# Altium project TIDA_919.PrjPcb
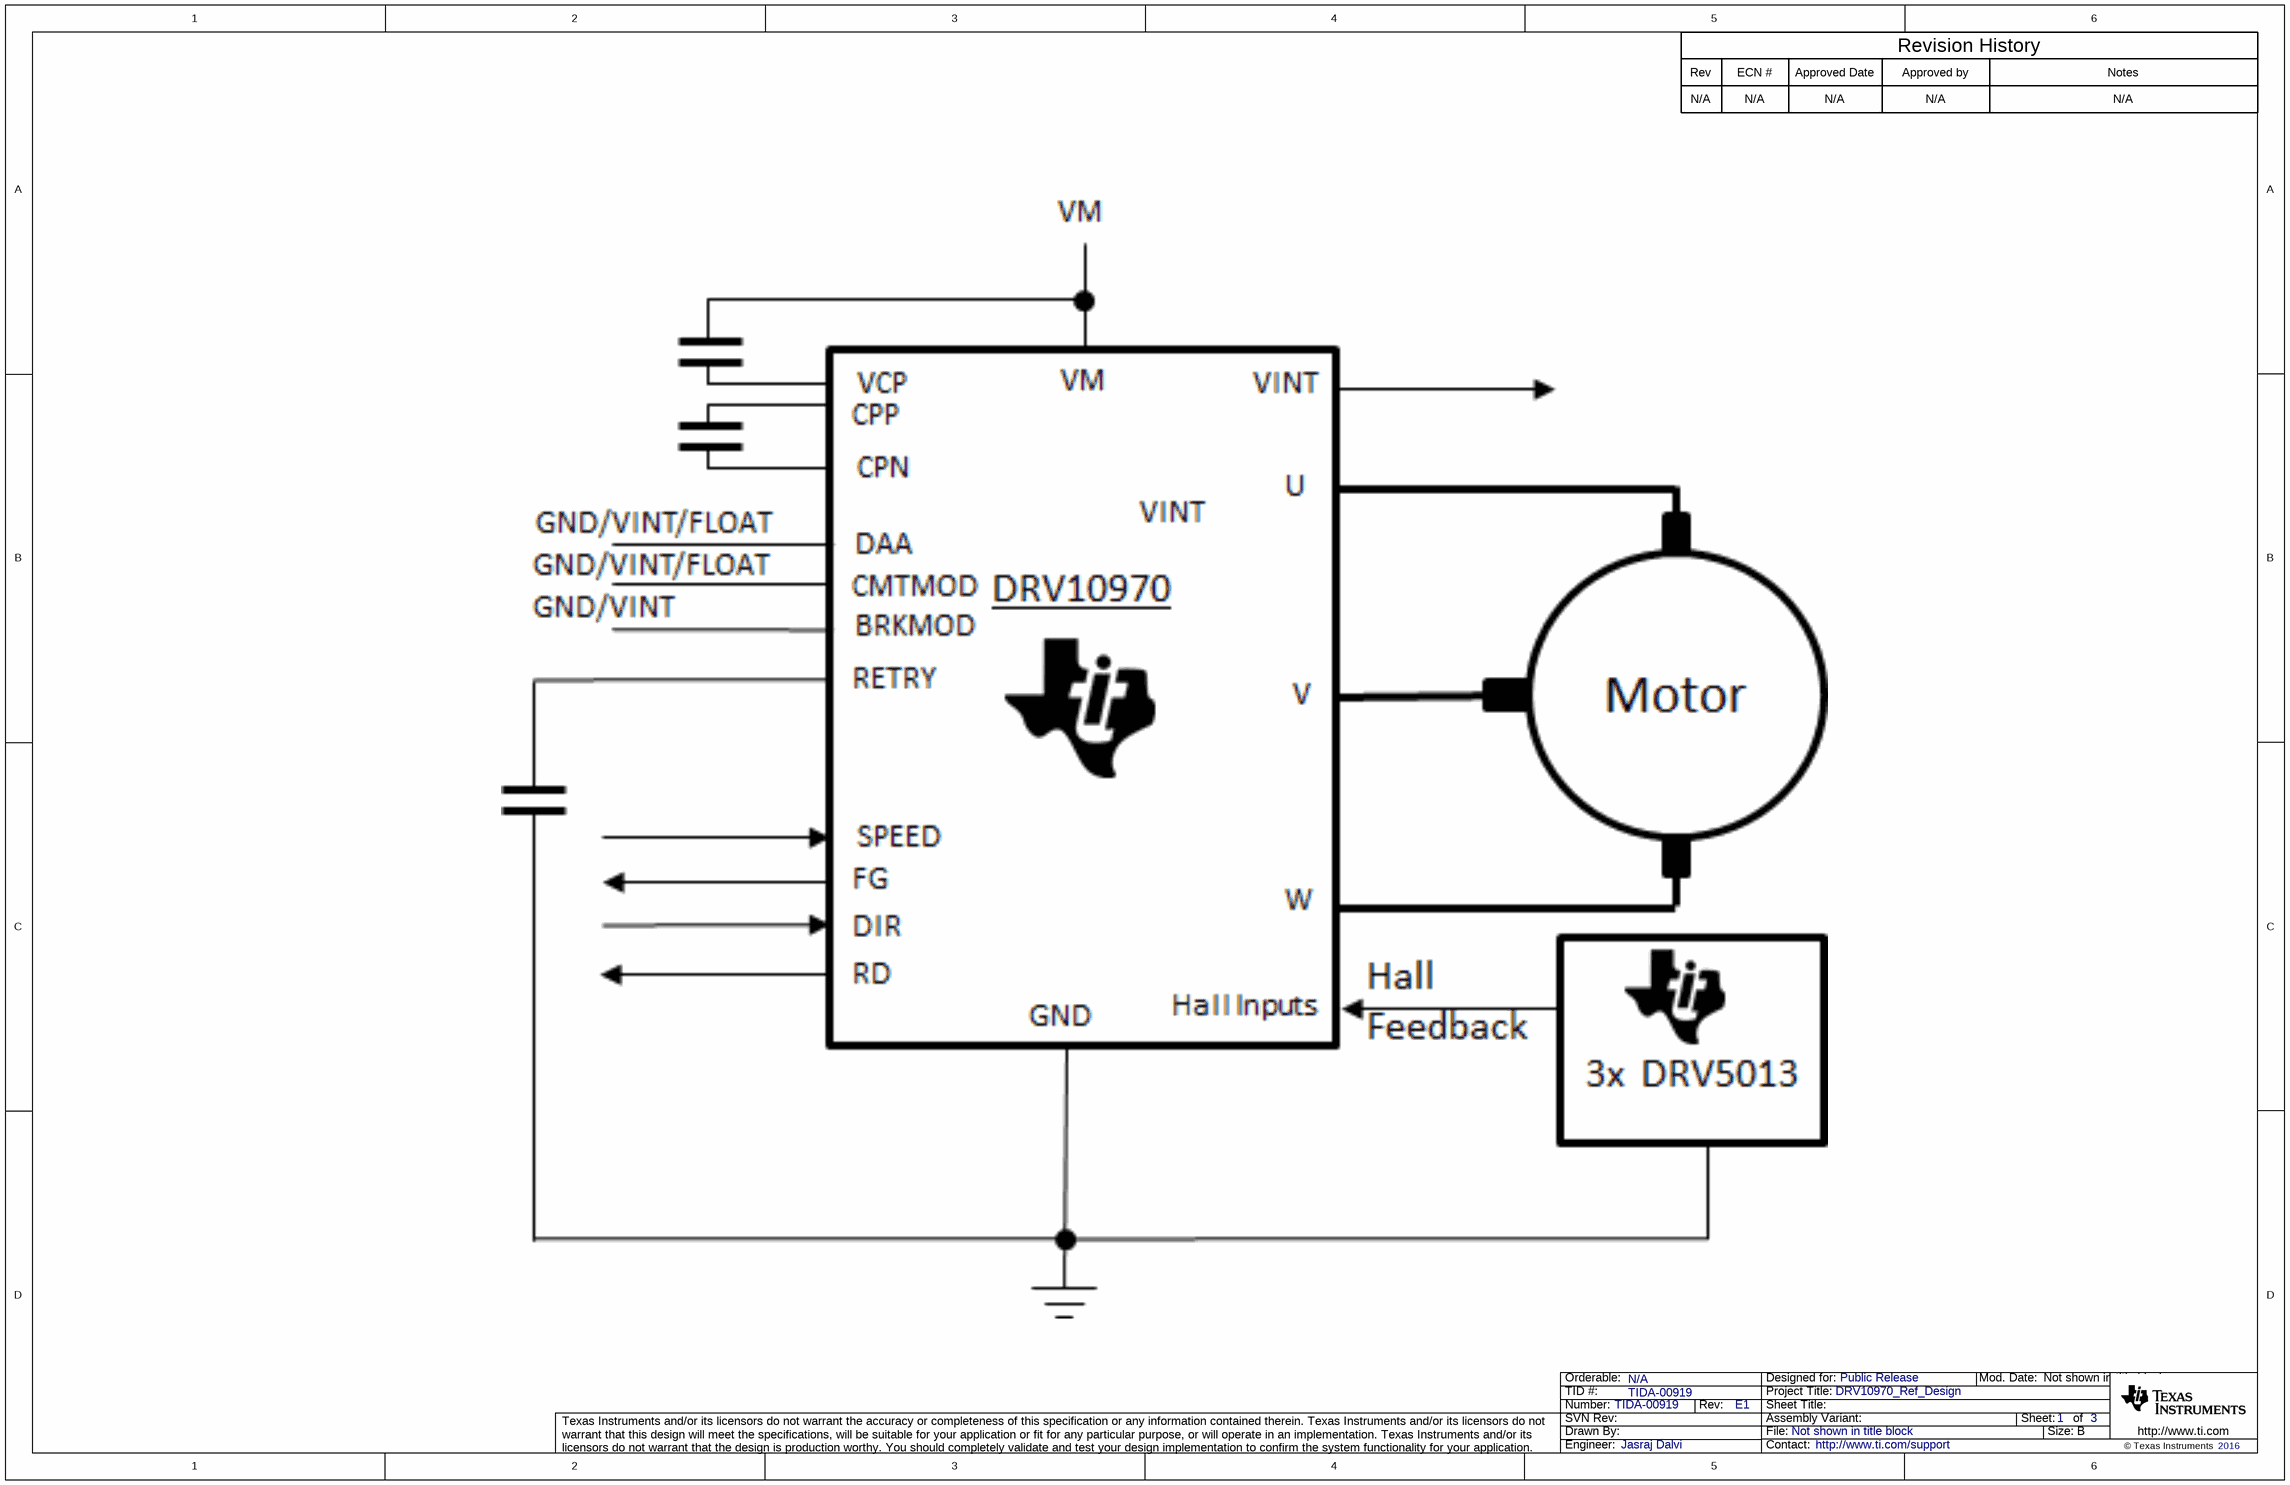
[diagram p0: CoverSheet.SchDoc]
CopyrightYear: 2016; EVM_Orderable: N/A; PCB_Layout: Jasraj Dalvi; PCB_Rev: E1; PRJ_Customer: Public Release; PRJ_Engineer: Jasraj Dalvi; PRJ_Number: TIDA-00919; PRJ_Title: DRV10970_Ref_Design; SCH_Rev: E1; TechSupport: http://www.ti.com/support; TID: TIDA-00919
3 sheets, 38 parts. Net scope: global (net labels, ports and power ports of the same name join across sheets).
Board file: TIDA00919E1.PcbDoc
Sheets:
  CoverSheet.SchDoc
  TIDA_00919.SchDoc
  TID_Hardware.SchDoc

## Sheet CoverSheet.SchDoc
size 431 x 279 mm; Date: Not shown in title block; ApprovedBy: Not shown in title block; CheckedBy: Not shown in title block; Author: Not shown in title block; CompanyName: Not shown in title block; Engineer: Not shown in title block; Organization: Not shown in title block; Address1: Not shown in title block; Address2: Not shown in title block; Address3: Not shown in title block; Address4: Not shown in title block; DocumentNumber: 1; Revision: Use project parameter SCH_Rev; SheetNumber: 1; SheetTotal: 3; PageSetup: Record=PageOptions¦CenterHorizontal=True¦CenterVertical=True¦PrintScale=1.00¦XCorrection=1.00¦YCorrection=1.00¦PrintKind=0¦BorderSize=5000000¦LeftOffset=0¦BottomOffset=0¦Orientation=2¦PaperLength=1000¦PaperWidth=1000¦Scale=100¦PaperSource=15¦PrintQuality=600¦MediaType=1¦DitherType=10¦PaperKind=Letter¦PrintScaleMode=1

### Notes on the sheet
- Rev
- N/A
- ECN #
- Approved Date
- Approved by
- Revision History
- Notes

## Sheet TIDA_00919.SchDoc
size 431 x 279 mm; Date: Not shown in title block; ApprovedBy: Not shown in title block; CheckedBy: Not shown in title block; Author: Not shown in title block; CompanyName: Not shown in title block; Engineer: Not shown in title block; Organization: Not shown in title block; Address1: Not shown in title block; Address2: Not shown in title block; Address3: Not shown in title block; Address4: Not shown in title block; DocumentNumber: 1; Revision: Use project parameter SCH_Rev; SheetNumber: 2; SheetTotal: 3; PageSetup: Record=PageOptions¦CenterHorizontal=True¦CenterVertical=True¦PrintScale=0.62¦XCorrection=1.00¦YCorrection=1.00¦PrintKind=0¦BorderSize=5000000¦LeftOffset=0¦BottomOffset=0¦Orientation=2¦PaperLength=1000¦PaperWidth=1000¦Scale=100¦PaperSource=15¦PrintQuality=600¦MediaType=1¦DitherType=10¦PrintScaleMode=1¦PaperKind=Letter
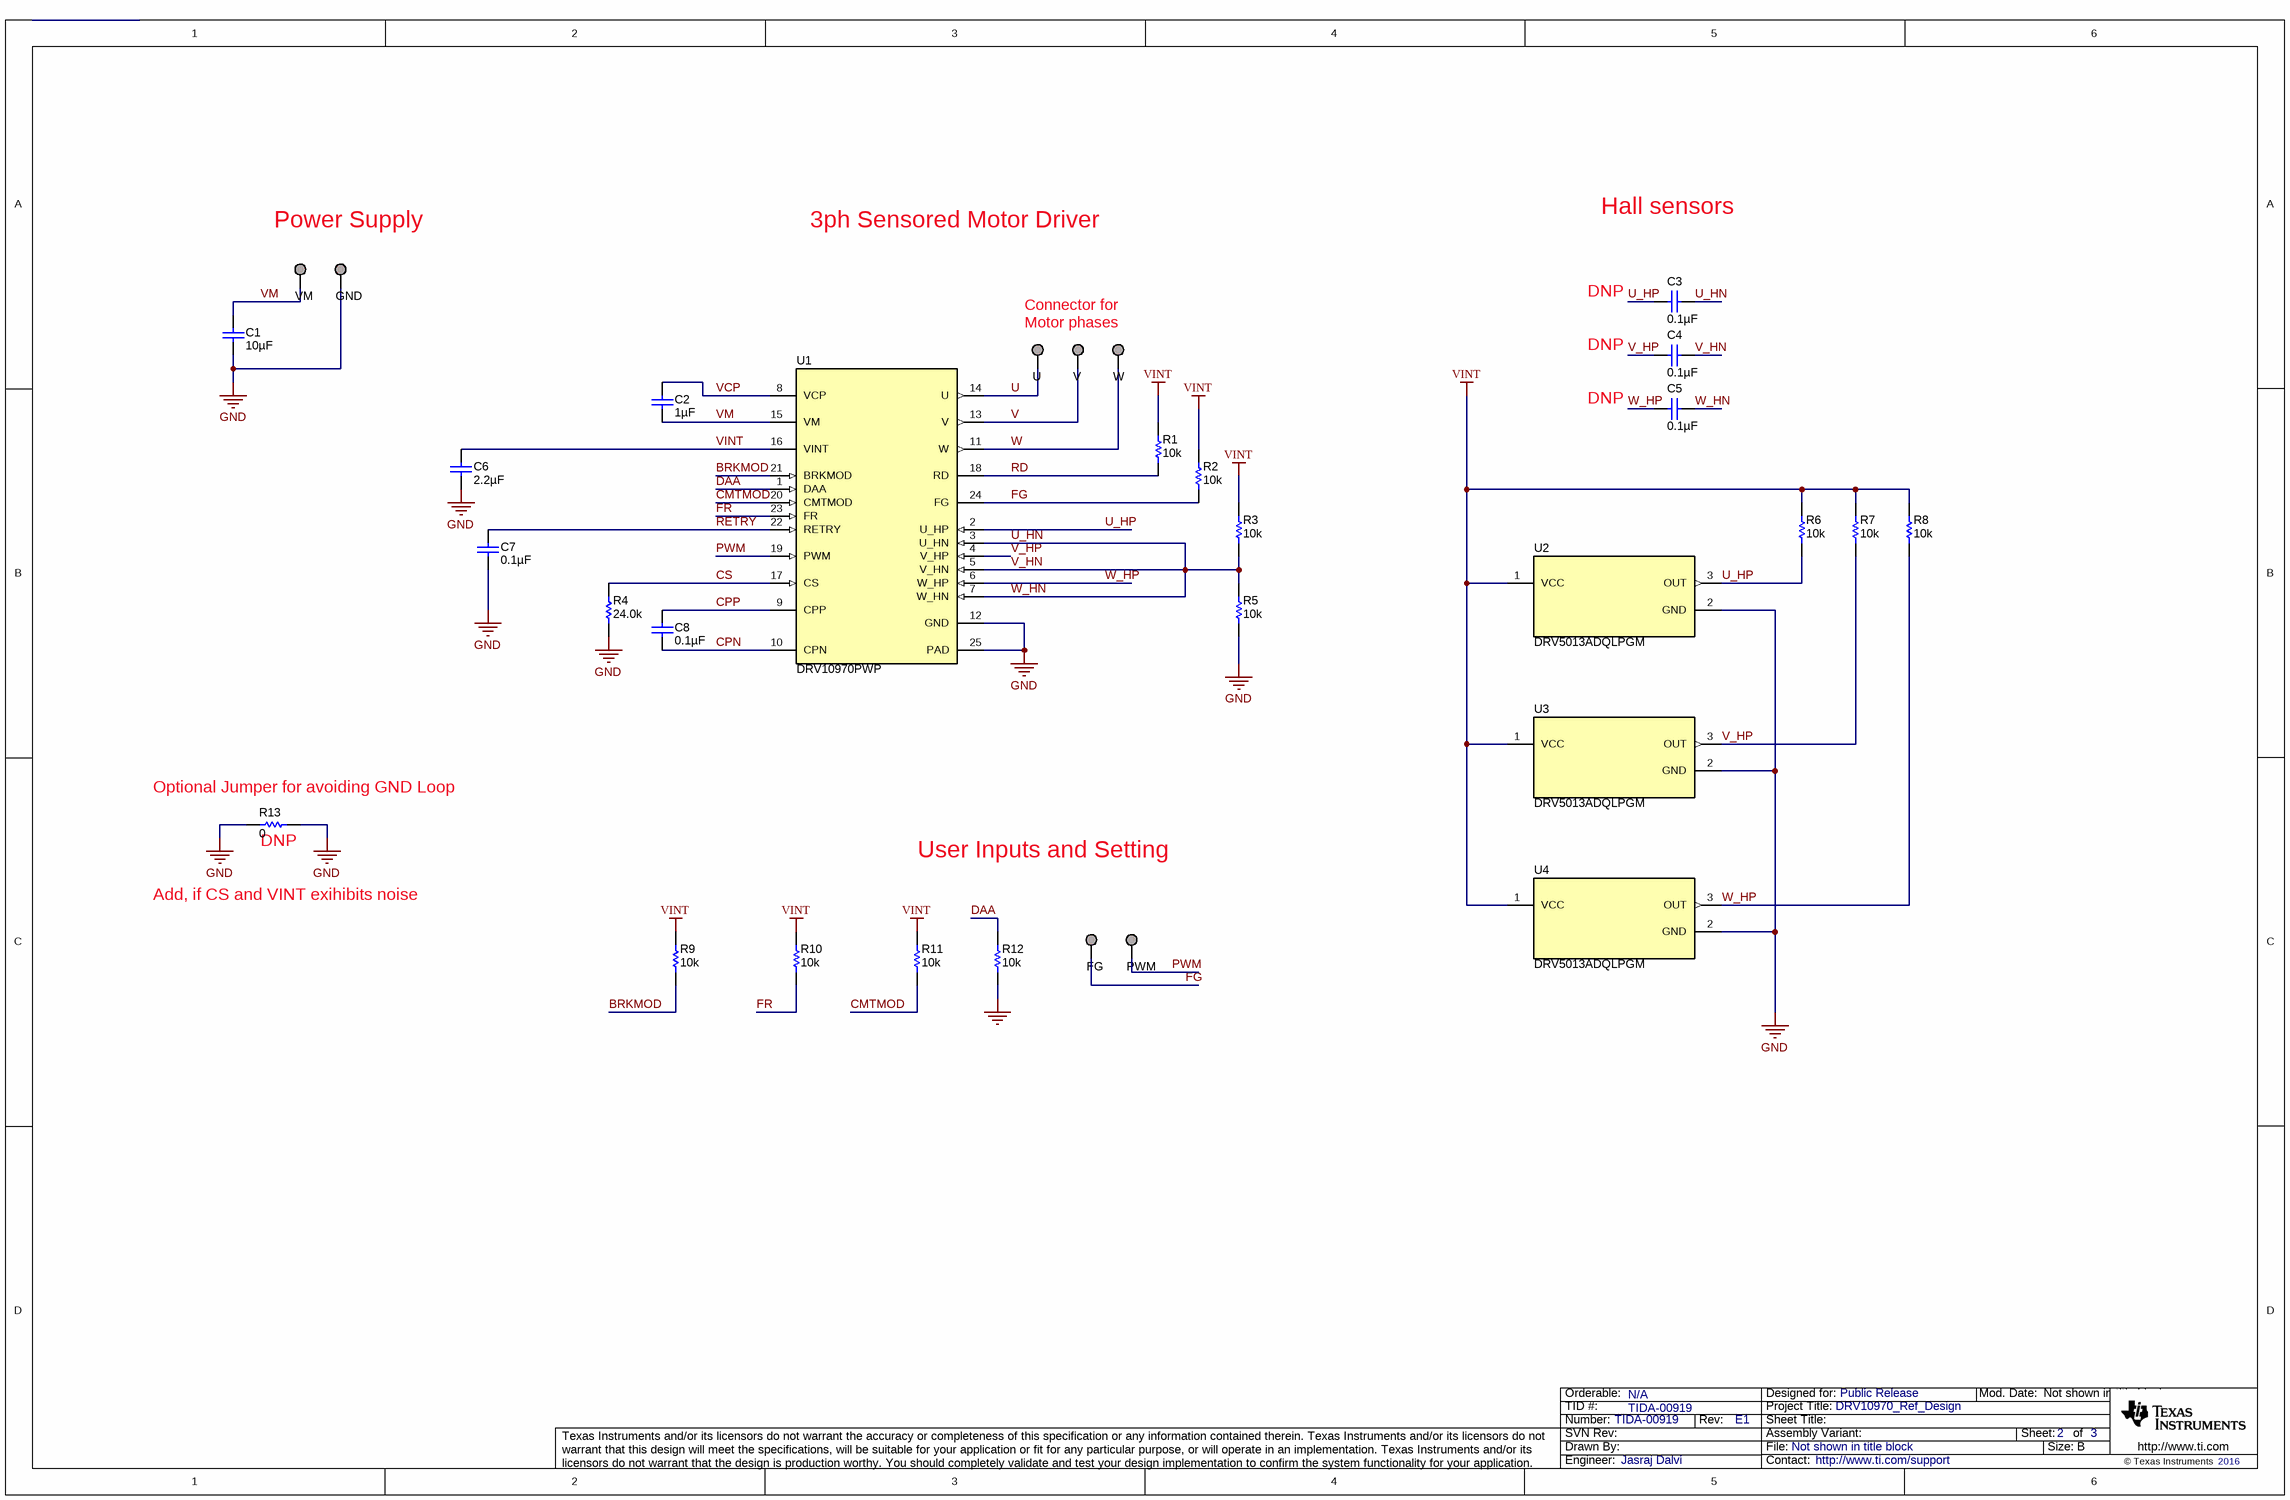
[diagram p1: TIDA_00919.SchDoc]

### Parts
C1  ValueDisplayed: 10µF  [1210_280]  (hidden comment: C3225X7R1H106M250AC)
C2  ValueDisplayed: 1µF  [1206]  (hidden comment: C3216X7R1E105K085AA)
C3  ValueDisplayed: 0.1µF  [0603]  (hidden comment: C0603C104M4RACTU)
C4  ValueDisplayed: 0.1µF  [0603]  (hidden comment: C0603C104M4RACTU)
C5  ValueDisplayed: 0.1µF  [0603]  (hidden comment: C0603C104M4RACTU)
C6  ValueDisplayed: 2.2µF  [0603]  (hidden comment: C0603C225K8PACTU)
C7  ValueDisplayed: 0.1µF  [0805_HV]  (hidden comment: CC0805KRX7R8BB104)
C8  ValueDisplayed: 0.1µF  [0603]  (hidden comment: 06033C104KAT2A)
FG  TESTPOINT  [Keystone_1402-3]  (value not drawn)  (no BOM)
GND  TESTPOINT  [Keystone_1402-3]  (value not drawn)  (no BOM)
PWM  TESTPOINT  [Keystone_1402-3]  (value not drawn)  (no BOM)
R1  ValueDisplayed: 10k  [0603]  (hidden comment: CRCW060310K0JNEA)
R2  ValueDisplayed: 10k  [0603]  (hidden comment: CRCW060310K0JNEA)
R3  ValueDisplayed: 10k  [1206]  (hidden comment: CRCW120610K0JNEA)
R4  ValueDisplayed: 24.0k  [0805_HV]  (hidden comment: RT0805BRD0724KL)
R5  ValueDisplayed: 10k  [0603]  (hidden comment: CRCW060310K0JNEA)
R6  ValueDisplayed: 10k  [1206]  (hidden comment: CRCW120610K0JNEA)
R7  ValueDisplayed: 10k  [1206]  (hidden comment: CRCW120610K0JNEA)
R8  ValueDisplayed: 10k  [1206]  (hidden comment: CRCW120610K0JNEA)
R9  ValueDisplayed: 10k  [0603]  (hidden comment: CRCW060310K0JNEA)
R10  ValueDisplayed: 10k  [0603]  (hidden comment: CRCW060310K0JNEA)
R11  ValueDisplayed: 10k  [0603]  (hidden comment: CRCW060310K0JNEA)
R12  ValueDisplayed: 10k  [0603]  (hidden comment: CRCW060310K0JNEA)
R13  ValueDisplayed: 0  [0805_HV]  (hidden comment: CRCW08050000Z0EA)
U  TESTPOINT  [Keystone_1402-3]  (value not drawn)  (no BOM)
U1  DRV10970PWP  [PWP0024D_N]
U2  DRV5013ADQLPGM  [LPG0003A]
U3  DRV5013ADQLPGM  [LPG0003A]
U4  DRV5013ADQLPGM  [LPG0003A]
V  TESTPOINT  [Keystone_1402-3]  (value not drawn)  (no BOM)
VM  TESTPOINT  [Keystone_1402-3]  (value not drawn)  (no BOM)
W  TESTPOINT  [Keystone_1402-3]  (value not drawn)  (no BOM)

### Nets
GND: C1.2 C6.2 C7.2 GND.1 R4.1 R5.1 R12.1 R13.1 R13.2 U1.12(GND) U1.25(PAD) U2.2(GND) U3.2(GND) U4.2(GND)
VINT: C6.1 R1.2 R2.2 R3.2 R6.2 R7.2 R8.2 R9.2 R10.2 R11.2 U1.16(VINT) U2.1(VCC) U3.1(VCC) U4.1(VCC)
BRKMOD: R9.1 U1.21(BRKMOD)
CMTMOD: R11.1 U1.20(CMTMOD)
CPN: C8.2 U1.10(CPN)
CPP: C8.1 U1.9(CPP)
CS: R4.2 U1.17(CS)
DAA: R12.2 U1.1(DAA)
FG: FG.1 R2.1 U1.24(FG)
FR: R10.1 U1.23(FR)
PWM: PWM.1 U1.19(PWM)
RD: R1.1 U1.18(RD)
RETRY: C7.1 U1.22(RETRY)
U: U.1 U1.14(U)
U_HN: C3.1 C4.1 C5.1 R3.1 R5.2 U1.3(U_HN) U1.5(V_HN) U1.7(W_HN)  [also labelled V_HN, W_HN]
U_HP: C3.2 R6.1 U1.2(U_HP) U2.3(OUT)
V: U1.13(V) V.1
V_HP: C4.2 R7.1 U1.4(V_HP) U3.3(OUT)
VCP: C2.1 U1.8(VCP)
VM: C1.1 C2.2 U1.15(VM) VM.1
W: U1.11(W) W.1
W_HP: C5.2 R8.1 U1.6(W_HP) U4.3(OUT)

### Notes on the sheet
- Power Supply
- 3ph Sensored Motor Driver
- Hall sensors
- Connector for
- DNP
- Motor phases
- (near R13) Optional Jumper for avoiding GND Loop
- (near R13) DNP
- Add, if CS and VINT exihibits noise
- User Inputs and Setting

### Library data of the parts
C1 = C3225X7R1H106M250AC: CAP, CERM, 10 µF, 50 V, +/- 20%, X7R, 1210; Manufacturer: TDK; Polarized: N; CompType: Capacitor; Value: 10uF; U/M: EA; Cap_F: 0.00001; Tolerance_%: 20; Value1: Unknown; VDC_V: 50; Value2: 50V; TaMin_C: -55; TaMax_C: 125; Cap_Case: 1210
C2 = C3216X7R1E105K085AA: CAP, CERM, 1 µF, 25 V, +/- 10%, X7R, 1206; Manufacturer: TDK; Polarized: N; CompType: Capacitor; Value: 1uF; U/M: EA; Cap_F: 0.000001; Tolerance_%: 10; ESR_ohm: 0.01; Value1: 0.01 ohm; VDC_V: 25; Value2: 25V; TaMin_C: -55; TaMax_C: 125; AEC Category: Q200
C3-C5 = C0603C104M4RACTU: CAP, CERM, 0.1 µF, 16 V, +/- 20%, X7R, 0603; Manufacturer: Kemet; Polarized: N; CompType: Capacitor; Value: 0.1uF; U/M: EA; Cap_F: 0.0000001; Tolerance_%: 20; Value1: Unknown; VDC_V: 16; Value2: 16V; TaMin_C: -55; TaMax_C: 125; AEC Category: Q200
C6 = C0603C225K8PACTU: CAP, CERM, 2.2 µF, 10 V, +/- 10%, X5R, 0603; Manufacturer: Kemet; Polarized: N; CompType: Capacitor; Value: 2.2uF; U/M: EA; Cap_F: 0.0000022; Tolerance_%: 10; Value1: Unknown; Value2: 10V; TaMin_C: -55; TaMax_C: 85; AEC Category: Q200
C7 = CC0805KRX7R8BB104: CAP, CERM, 0.1 µF, 25 V, +/- 10%, X7R, 0805; Manufacturer: Yageo America; Polarized: N; CompType: Capacitor; Value: 0.1uF; U/M: EA; Cap_F: 0.0000001; Tolerance_%: 10; Value1: Unknown; VDC_V: 25; Value2: 25V; TaMin_C: -55; TaMax_C: 125; Cap_Case: 0805; AEC Category: Q200
C8 = 06033C104KAT2A: CAP, CERM, 0.1 µF, 25 V, +/- 10%, X7R, 0603; Manufacturer: AVX; Polarized: N; CompType: Capacitor; Value: 0.1uF; U/M: EA; Cap_F: 0.0000001; Tolerance_%: 10; ESR_ohm: 0.05; Value1: 0.05 ohm; VDC_V: 25; Value2: 25V; TaMin_C: -55; TaMax_C: 125; AEC Category: Q200
FG GND PWM U V VM W = 1402-3: Micro Pin, Gold, Swage Mount; Manufacturer: Keystone; CompType: Standoff
R1 R2 R5 R9-R12 = CRCW060310K0JNEA: RES, 10 k, 5%, 0.1 W, 0603; Manufacturer: Vishay-Dale; CompType: Resistor; Value: 10k; Res_ohm: 10000; Value_Code: 10k0; Tolerance_%: 5; Power_W: 0.1; Value2: 0.1W; VDC_V: 75; TempCo: 200 ppm/C; EIA_Code: E24; U/M: EA; AEC Category: Q200
R3 R6-R8 = CRCW120610K0JNEA: RES, 10 k, 5%, 0.25 W, 1206; Manufacturer: Vishay-Dale; CompType: Resistor; Value: 10k; Res_ohm: 10000; Value_Code: 10k0; Tolerance_%: 5; Power_W: 0.25; Value2: 0.25W; VDC_V: 200; TempCo: 200 ppm/C; EIA_Code: E24; U/M: EA; AEC Category: Q200
R4 = RT0805BRD0724KL: RES, 24.0 k, 0.1%, 0.125 W, 0805; Manufacturer: Yageo America; CompType: Resistor; Value: 24.0k; Res_ohm: 24000; Value_Code: 24k0; Tolerance_%: 0.1; Power_W: 0.125; Value2: 0.125W; VDC_V: 150; TempCo: 25 ppm/C; EIA_Code: E192; U/M: EA; AEC Category: Q200
R13 = CRCW08050000Z0EA: RES, 0, 5%, 0.125 W, 0805; Manufacturer: Vishay-Dale; CompType: Resistor; Value: 0; Value_Code: 0000; Tolerance_%: 5; Power_W: 0.125; Value2: 0.125W; VDC_V: 150; TempCo: 200 ppm/C; EIA_Code: E24; U/M: EA; AEC Category: Q200
U1 = DRV10970PWP: 3-Phase Brushless DC Motor Driver, PWP0024D; Manufacturer: Texas Instruments; SymbolCreator: Altium; CompType: IC; U/M: EA
U2-U4 = DRV5013ADQLPGM: Digital-Latch Hall Effect Sensor, LPG0003A; Manufacturer: Texas Instruments; SymbolCreator: a0799628; CompType: IC; U/M: EA

## Sheet TID_Hardware.SchDoc
size 431 x 279 mm; Date: Not shown in title block; ApprovedBy: Not shown in title block; CheckedBy: Not shown in title block; Author: Not shown in title block; CompanyName: Not shown in title block; Engineer: Not shown in title block; Organization: Not shown in title block; Address1: Not shown in title block; Address2: Not shown in title block; Address3: Not shown in title block; Address4: Not shown in title block; DocumentNumber: 1; Revision: Use project parameter SCH_Rev; SheetNumber: 3; SheetTotal: 3; PageSetup: Record=PageOptions¦CenterHorizontal=True¦CenterVertical=True¦PrintScale=1.00¦XCorrection=1.00¦YCorrection=1.00¦PrintKind=0¦BorderSize=5000000¦LeftOffset=0¦BottomOffset=0¦Orientation=2¦PaperLength=1000¦PaperWidth=1000¦Scale=100¦PaperSource=15¦PrintQuality=600¦MediaType=1¦DitherType=10¦PaperKind=Letter¦PrintScaleMode=1
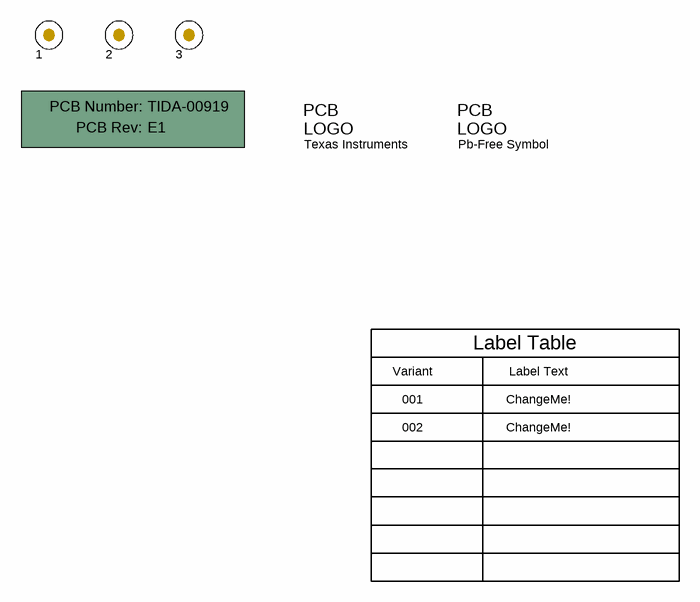
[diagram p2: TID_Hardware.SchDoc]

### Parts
1  Fiducial  [Fiducial10-20]  (value not drawn)
2  Fiducial  [Fiducial10-20]  (value not drawn)
3  Fiducial  [Fiducial10-20]  (value not drawn)
4  Texas Instruments  [TI_Horizontal_Overlay_Small]  (no BOM)
5  Pb-Free Symbol  [Pb-Free_Overlay_Small]  (no BOM)
!PCB1  Printed Circuit Board  (value not drawn)  (mechanical)

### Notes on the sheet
- Variant
- Label Table
- Label Text
- 001
- 002
- ChangeMe!

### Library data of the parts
1-3 = Fiducial: Fiducial mark.  There is nothing to buy or mount.; SymbolCreator: codlsc
4 = TI_Logo: Texas Instrument Corporate Signature; SymbolCreator: codlsc
5 = Pb-Free: SymbolCreator: a0412235
!PCB1 = PCB: Manufacturer: Any; PartNumber: TIDA-00919; SymbolCreator: a0412235

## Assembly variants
001: not fitted FID1 FID2 FID3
